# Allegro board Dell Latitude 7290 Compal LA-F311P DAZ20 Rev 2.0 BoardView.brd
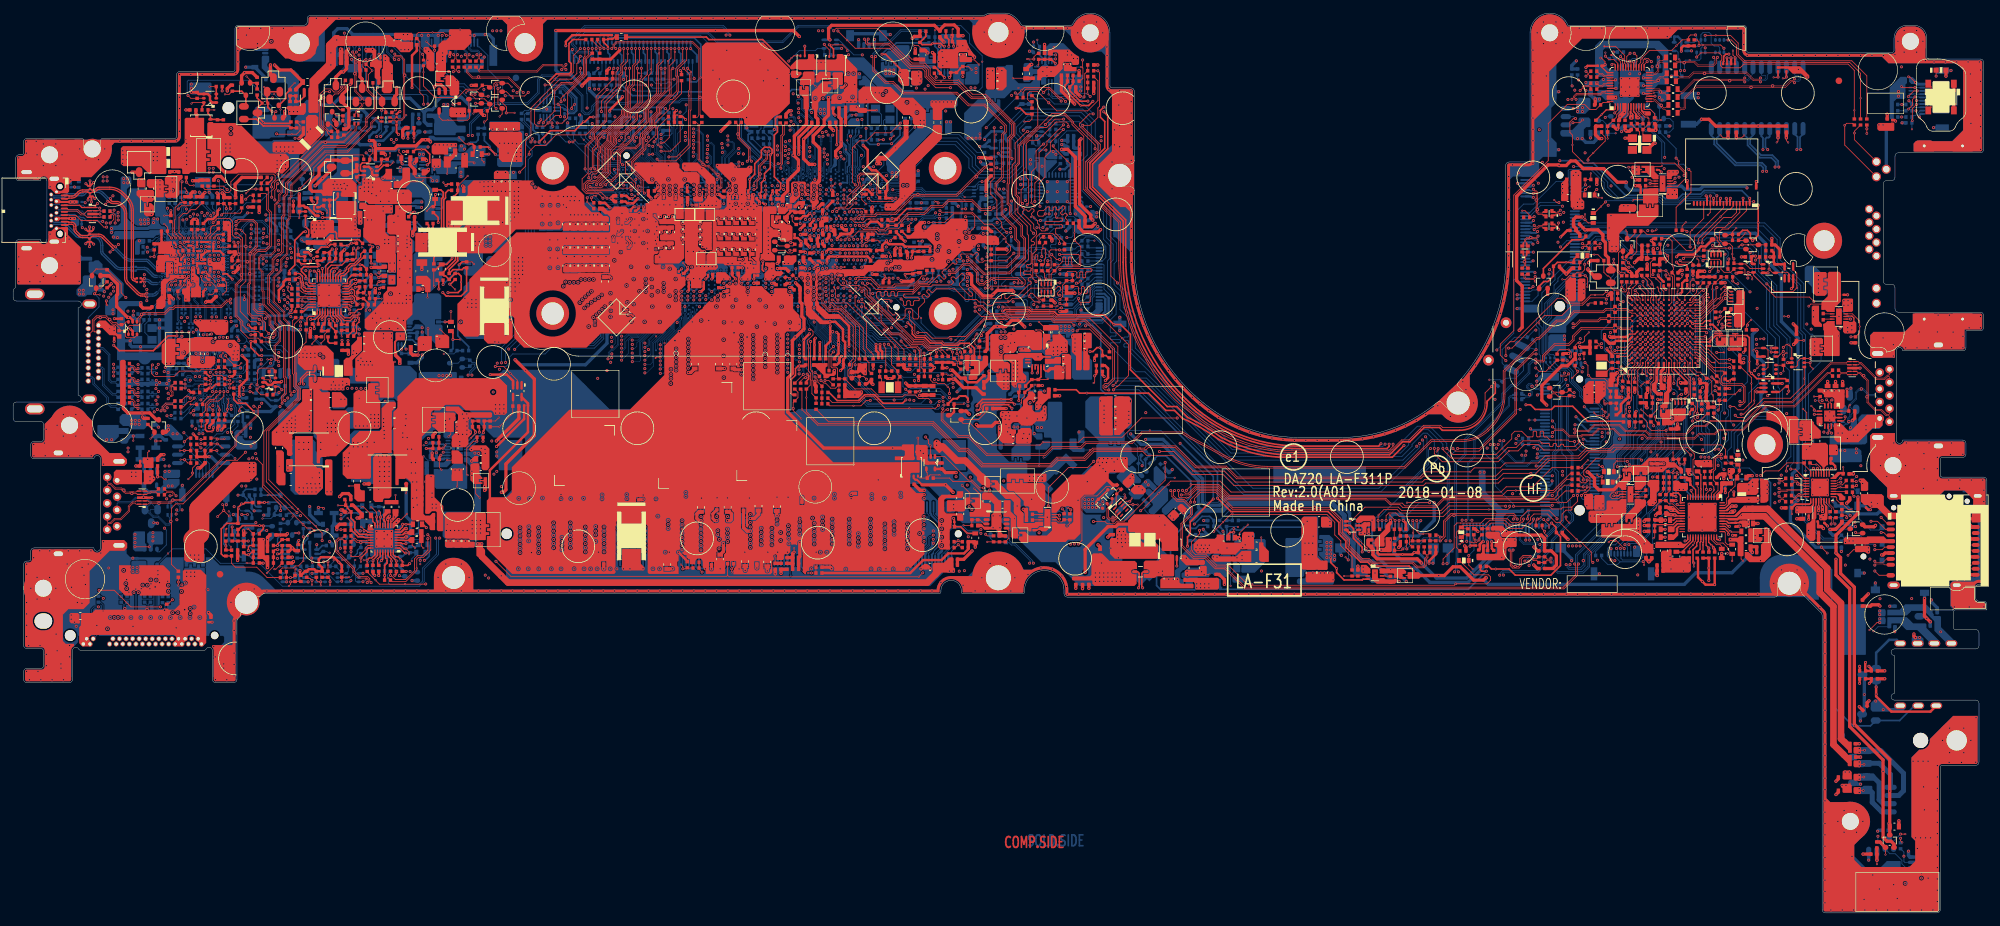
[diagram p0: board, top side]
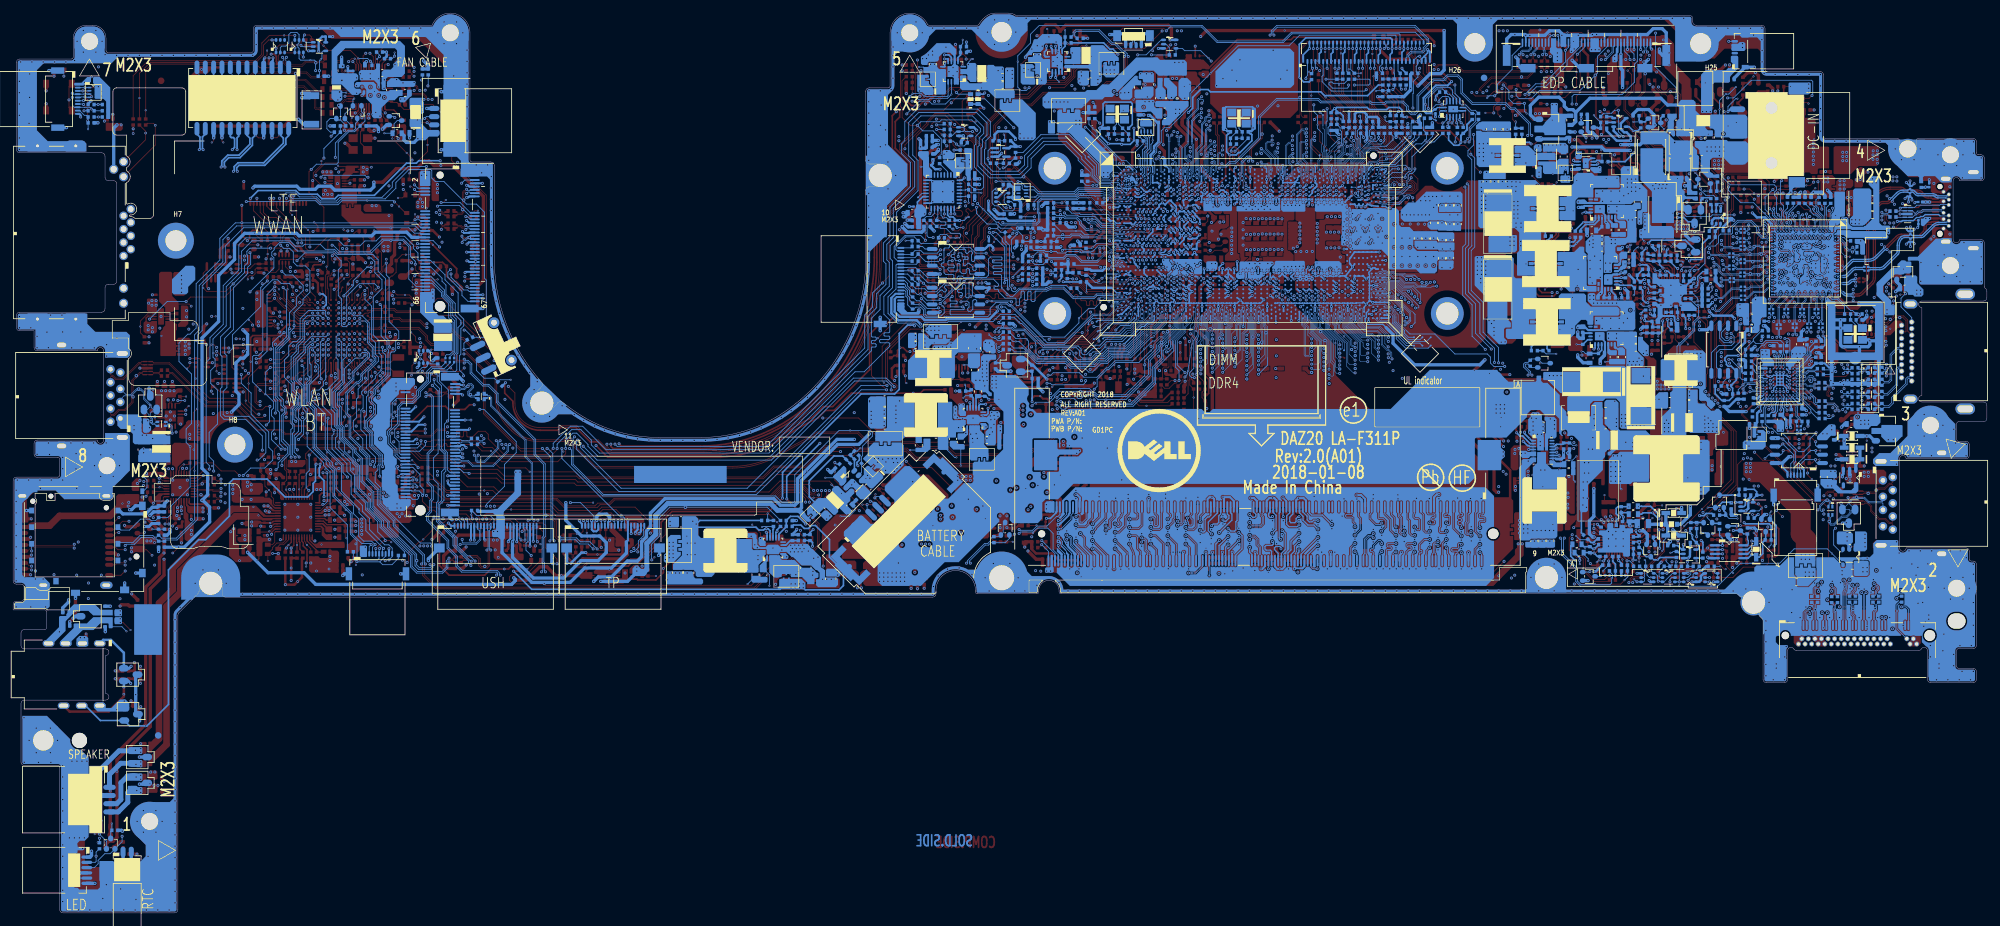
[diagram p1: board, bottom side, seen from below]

Outline 300.7 x 137.2 mm; copper layers: TOP, GND1, IN1, GND2, IN2, IN3, VCC, IN4, GND3, BOTTOM. Coordinates in mm from the lower left corner of the outline.

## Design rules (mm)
net group 20: nets DDR_DRAMRST#_R EMMC_RCOMP
net group AR_DP1_CTRL_CLK: nets AR_DP1_CTRL_CLK AR_DP1_CTRL_DATA
net group CPU_DP1_0: nets CPU_DP1_N0 CPU_DP1_P0
net group CPU_DP1_0_C: nets CPU_DP1_N0_C CPU_DP1_P0_C
net group CPU_DP1_1_C: nets CPU_DP1_N1_C CPU_DP1_P1_C
net group CPU_DP1_2: nets CPU_DP1_N2 CPU_DP1_P2
net group CPU_DP1_2_C: nets CPU_DP1_N2_C CPU_DP1_P2_C
net group CPU_DP1_3: nets CPU_DP1_N3 CPU_DP1_P3
net group CPU_DP1_3_C: nets CPU_DP1_N3_C CPU_DP1_P3_C
net group CPU_DP1_AUX_C: nets CPU_DP1_AUXN_C CPU_DP1_AUXP_C
net group DIFFPAIR2: nets PCIE_PRX_DTX_N1 PCIE_PRX_DTX_P1
net group DIFFPAIR4: nets USB20_N9 USB20_P9
net group DIFFPAIR5: nets USB3_PRX_DTX_N6 USB3_PRX_DTX_P6
net group DIFFPAIR6: nets USB3_PTX_DRX_N6 USB3_PTX_DRX_P6
net group DIFFPAIR7: nets TBTA_USB20_N_R TBTA_USB20_P_R
net group DIFFPAIR8: nets USB20_N9_R USB20_P9_R
net group DIFFPAIR9: nets SW_USB20_N9 SW_USB20_P9
net group DIFFPAIR17: nets N18278920 N18278998
net group DIFFPAIR18: nets USB3_PTX_C_DRX_N6 USB3_PTX_C_DRX_P6
net group HDMI_CTRL_CLK: nets HDMI_CTRL_CLK HDMI_CTRL_DATA
net group INT_SPK_L: nets INT_SPK_L+ INT_SPK_L-
net group INT_SPK_R: nets INT_SPK_R+ INT_SPK_R-
net group INT_SPKR_L: nets INT_SPKR_L+ INT_SPKR_L-
net group INT_SPKR_R: nets INT_SPKR_R+ INT_SPKR_R-
net group ISH_I2C2_SCL: nets ISH_I2C2_SCL ISH_I2C2_SDA
net group LAN_MDI0: nets LAN_MDIN0 LAN_MDIP0
net group LAN_MDI0_L: nets LAN_MDIN0_L LAN_MDIP0_L
net group LAN_MDI1: nets LAN_MDIN1 LAN_MDIP1
net group LAN_MDI1_L: nets LAN_MDIN1_L LAN_MDIP1_L
net group LAN_MDI2: nets LAN_MDIN2 LAN_MDIP2
net group LAN_MDI2_L: nets LAN_MDIN2_L LAN_MDIP2_L
net group LAN_MDI3: nets LAN_MDIN3 LAN_MDIP3
net group LAN_MDI3_L: nets LAN_MDIN3_L LAN_MDIP3_L
net group LPSS_UART2_XD: nets LPSS_UART2_RXD LPSS_UART2_TXD
net group MEM_SMB: nets MEM_SMBCLK MEM_SMBDATA
net group MSCLK: nets MSCLK MSDATA
net group PBAT_CHARGER_SMB: nets PBAT_CHARGER_SMBCLK PBAT_CHARGER_SMBDAT
net group PCIE_PRX_C_DTX_5: nets PCIE_PRX_C_DTX_N5 PCIE_PRX_C_DTX_P5
net group PCIE_PRX_C_DTX_6: nets PCIE_PRX_C_DTX_N6 PCIE_PRX_C_DTX_P6
net group PCIE_PRX_C_DTX_7: nets PCIE_PRX_C_DTX_N7 PCIE_PRX_C_DTX_P7
net group PCIE_PRX_C_DTX_8: nets PCIE_PRX_C_DTX_N8 PCIE_PRX_C_DTX_P8
net group PCIE_PRX_DTX_3: nets PCIE_PRX_DTX_N3 PCIE_PRX_DTX_P3
net group PCIE_PRX_DTX_5: nets PCIE_PRX_DTX_N5 PCIE_PRX_DTX_P5
net group PCIE_PRX_DTX_6: nets PCIE_PRX_DTX_N6 PCIE_PRX_DTX_P6
net group PCIE_PRX_DTX_7: nets PCIE_PRX_DTX_N7 PCIE_PRX_DTX_P7
net group PCIE_PRX_DTX_8: nets PCIE_PRX_DTX_N8 PCIE_PRX_DTX_P8
net group PCIE_PTX_C_DRX_3: nets PCIE_PTX_C_DRX_N3 PCIE_PTX_C_DRX_P3
net group PCIE_PTX_C_DRX_5: nets PCIE_PTX_C_DRX_N5 PCIE_PTX_C_DRX_P5
net group PCIE_PTX_C_DRX_6: nets PCIE_PTX_C_DRX_N6 PCIE_PTX_C_DRX_P6
net group PCIE_PTX_C_DRX_7: nets PCIE_PTX_C_DRX_N7 PCIE_PTX_C_DRX_P7
net group PCIE_PTX_C_DRX_8: nets PCIE_PTX_C_DRX_N8 PCIE_PTX_C_DRX_P8
net group PCIE_PTX_DRX_3: nets PCIE_PTX_DRX_N3 PCIE_PTX_DRX_P3
net group PCIE_PTX_DRX_5: nets PCIE_PTX_DRX_N5 PCIE_PTX_DRX_P5
net group PCIE_PTX_DRX_6: nets PCIE_PTX_DRX_N6 PCIE_PTX_DRX_P6
net group PCIE_PTX_DRX_7: nets PCIE_PTX_DRX_N7 PCIE_PTX_DRX_P7
net group PCIE_PTX_DRX_8: nets PCIE_PTX_DRX_N8 PCIE_PTX_DRX_P8
net group REM_DIODE1: nets REM_DIODE1_N REM_DIODE1_P
net group REM_DIODE2: nets REM_DIODE2_N REM_DIODE2_P
net group REM_DIODE4: nets REM_DIODE4_N REM_DIODE4_P
net group RJ45_MDI0: nets RJ45_MDIN0 RJ45_MDIP0
net group RJ45_MDI1: nets RJ45_MDIN1 RJ45_MDIP1
net group RJ45_MDI2: nets RJ45_MDIN2 RJ45_MDIP2
net group RJ45_MDI3: nets RJ45_MDIN3 RJ45_MDIP3
net group SENSE: nets VCC_GT_SENSE VSS_GT_SENSE
net group SML0_SMB: nets SML0_SMBCLK SML0_SMBDATA
net group SML1_SMB: nets SML1_SMBCLK SML1_SMBDATA
net group TBTA_AUX: nets TBTA_AUXN TBTA_AUXP
net group TBTA_AUX_C: nets TBTA_AUXN_C TBTA_AUXP_C
net group TBTA_LSX_R: nets TBTA_LSRX_R TBTA_LSTX_R
net group TBTA_USB20: nets TBTA_USB20_N TBTA_USB20_P
net group UPD1_SMBD: nets UPD1_SMBCLK_Q UPD1_SMBDAT_Q
net group USB3_PRX_DTX_2: nets USB3_PRX_DTX_N2 USB3_PRX_DTX_P2
net group USB3_PRX_DTX_3: nets USB3_PRX_DTX_N3 USB3_PRX_DTX_P3
net group USB3_PRX_L_DTX_2: nets USB3_PRX_L_DTX_N2 USB3_PRX_L_DTX_P2
net group USB3_PTX_C_DRX_2: nets USB3_PTX_C_DRX_N2 USB3_PTX_C_DRX_P2
net group USB3_PTX_C_DRX_3: nets USB3_PTX_C_DRX_N3 USB3_PTX_C_DRX_P3
net group USB3_PTX_DRX_2: nets USB3_PTX_DRX_N2 USB3_PTX_DRX_P2
net group USB3_PTX_DRX_3: nets USB3_PTX_DRX_N3 USB3_PTX_DRX_P3
net group USB3_PTX_L_DRX_2: nets USB3_PTX_L_DRX_N2 USB3_PTX_L_DRX_P2
net group USB20_1: nets USB20_N1 USB20_P1
net group USB20_2: nets USB20_N2 USB20_P2
net group USB20_2_R: nets USB20_N2_R USB20_P2_R
net group USB20_4: nets USB20_N4 USB20_P4
net group USB20_4_L: nets USB20_N4_L USB20_P4_L
net group USB20_5: nets USB20_N5 USB20_P5
net group USB20_5_R: nets USB20_N5_R USB20_P5_R
net group USB20_7: nets USB20_N7 USB20_P7
net group USB20_7_L: nets USB20_N7_L USB20_P7_L
net group USB20_8: nets USB20_N8 USB20_P8
net group USB20_8_R: nets USB20_N8_R USB20_P8_R
net group USB20_10: nets USB20_N10 USB20_P10
net group VCCSENSE: nets VCCSENSE VSSSENSE
net group VSA_SEN: nets VSA_SEN+ VSA_SEN-
net group VSSIO_SENSE: nets VCCIO_SENSE VSSIO_SENSE
net group 10: nets AUD_HP_NB_SENSE AUD_HP_OUT_L AUD_HP_OUT_L1 AUD_HP_OUT_R AUD_HP_OUT_R1 AUD_SENSE_A
net group 15: nets BC_CLK_ECE1117 CLK_TP_SIO_R CPU_DP2_CTRL_CLK CPU_XDP_TCLK DAT_TP_SIO_I2C_CLK DDR_XDP_WAN_SMBCLK DMIC_CLK0 ESPI_CLK_5105 HDA_BIT_CLK HDA_BIT_CLK_R I2C1_SCK_TP_R JTAG_CLK PCH_JTAG_TCK PCI_CLK_LPC1 SUSCLK SUSCLK_R TBT_I2C_SCL TBT_ROM_CLK WIGIG_32KHZ XCLK_BIASREF XDP_JTAGX
net group AR-90H: nets TBTA_RX1N TBTA_RX1P TBTA_RX2N TBTA_RX2P TBTA_TX1N TBTA_TX1N_C TBTA_TX1P TBTA_TX1P_C TBTA_TX2N TBTA_TX2N_C TBTA_TX2P TBTA_TX2P_C
net group AR-TBT: nets TBTA_BOT_N TBTA_BOT_N_R TBTA_BOT_P TBTA_BOT_P_R TBTA_LSRX TBTA_LSTX TBTA_TOP_N TBTA_TOP_N_R TBTA_TOP_P TBTA_TOP_P_R
net group AR_HDMI: nets AR_DP1_N0 AR_DP1_N1 AR_DP1_N2 AR_DP1_N3 AR_DP1_P0 AR_DP1_P1 AR_DP1_P2 AR_DP1_P3 HDMI_CLKN HDMI_CLKP HDMI_L_CLKN HDMI_L_CLKP HDMI_L_TX_N0 HDMI_L_TX_N1 HDMI_L_TX_N2 HDMI_L_TX_P0 HDMI_L_TX_P1 HDMI_L_TX_P2 HDMI_TX_N0 HDMI_TX_N1 HDMI_TX_N2 HDMI_TX_P0 HDMI_TX_P1 HDMI_TX_P2
net group ASYNC: nets H_CATERR# H_THERMTRIP# H_VCCST_PWRGD_XDP PCH_PLTRST# PCH_PLTRST#_5105 PCH_PLTRST#_AND PCH_PLTRST#_EC PLTRST_LAN# PLTRST_TPM# VCCST_PWRGD XDP_OBS0 XDP_OBS0_R XDP_OBS1 XDP_OBS1_R
net group CL_IAMT: nets PCH_CL_CLK1 PCH_CL_DATA1 PCH_CL_RST1#
net group DDR_XDP_WAN_SMB: nets DDR_XDP_WAN_SMBDAT
net group DDRA_CKE: nets DDR_A_CKE0 DDR_A_CKE1 DDR_A_CKE2 DDR_A_CKE3
net group DDRA_CLK: nets DDR_A_CLK0 DDR_A_CLK1 DDR_A_CLK#0 DDR_A_CLK#1
net group DDRA_CMD: nets DDR_A_ACT# DDR_A_ALERT# DDR_A_BA0 DDR_A_BA1 DDR_A_BG0 DDR_A_BG1 DDR_A_MA0 DDR_A_MA1 DDR_A_MA2 DDR_A_MA3 DDR_A_MA4 DDR_A_MA5 DDR_A_MA6 DDR_A_MA7 DDR_A_MA8 DDR_A_MA9 DDR_A_MA10 DDR_A_MA11 DDR_A_MA12 DDR_A_MA13 DDR_A_MA14 DDR_A_MA15 DDR_A_MA16 DDR_A_PARITY
net group DDRA_CTL: nets DDR_A_CS#0 DDR_A_CS#1 DDR_A_ODT0 DDR_A_ODT1
net group DDRA_D0: nets DDR_A_D0 DDR_A_D1 DDR_A_D2 DDR_A_D3 DDR_A_D4 DDR_A_D5 DDR_A_D6 DDR_A_D7
net group DDRA_D1: nets DDR_A_D8 DDR_A_D9 DDR_A_D10 DDR_A_D11 DDR_A_D12 DDR_A_D13 DDR_A_D14 DDR_A_D15
net group DDRA_D2: nets DDR_A_D16 DDR_A_D17 DDR_A_D18 DDR_A_D19 DDR_A_D20 DDR_A_D21 DDR_A_D22 DDR_A_D23
net group DDRA_D3: nets DDR_A_D24 DDR_A_D25 DDR_A_D26 DDR_A_D27 DDR_A_D28 DDR_A_D29 DDR_A_D30 DDR_A_D31
net group DDRA_D4: nets DDR_A_D32 DDR_A_D33 DDR_A_D34 DDR_A_D35 DDR_A_D36 DDR_A_D37 DDR_A_D38 DDR_A_D39
net group DDRA_D5: nets DDR_A_D40 DDR_A_D41 DDR_A_D42 DDR_A_D43 DDR_A_D44 DDR_A_D45 DDR_A_D46 DDR_A_D47
net group DDRA_D6: nets DDR_A_D48 DDR_A_D49 DDR_A_D50 DDR_A_D51 DDR_A_D52 DDR_A_D53 DDR_A_D54 DDR_A_D55
net group DDRA_D7: nets DDR_A_D56 DDR_A_D57 DDR_A_D58 DDR_A_D59 DDR_A_D60 DDR_A_D61 DDR_A_D62 DDR_A_D63
net group DDRA_DQS: nets DDR_A_DQS0 DDR_A_DQS1 DDR_A_DQS2 DDR_A_DQS3 DDR_A_DQS4 DDR_A_DQS5 DDR_A_DQS6 DDR_A_DQS7 DDR_A_DQS#0 DDR_A_DQS#1 DDR_A_DQS#2 DDR_A_DQS#3 DDR_A_DQS#4 DDR_A_DQS#5 DDR_A_DQS#6 DDR_A_DQS#7
net group DIFF_CLK: nets CLK_ITPXDP_N CLK_ITPXDP_N_R CLK_ITPXDP_P CLK_ITPXDP_P_R CLK_PCIE_N1 CLK_PCIE_N3 CLK_PCIE_N4 CLK_PCIE_N5 CLK_PCIE_P1 CLK_PCIE_P3 CLK_PCIE_P4 CLK_PCIE_P5
net group DMIC: nets DMIC_CLK_CODEC
net group DMIC_CLK: nets DMIC0
net group DP: nets CPU_DP1_AUXN CPU_DP1_AUXP CPU_DP1_N1 CPU_DP1_P1 CPU_DP2_AUXN CPU_DP2_AUXN_C CPU_DP2_AUXP CPU_DP2_AUXP_C CPU_DP2_N0 CPU_DP2_N0_C CPU_DP2_N1 CPU_DP2_N1_C CPU_DP2_N2 CPU_DP2_N2_C CPU_DP2_N3 CPU_DP2_N3_C CPU_DP2_P0 CPU_DP2_P0_C CPU_DP2_P1 CPU_DP2_P1_C CPU_DP2_P2 CPU_DP2_P2_C CPU_DP2_P3 CPU_DP2_P3_C
net group EDP: nets EDP_AUXN EDP_AUXN_C EDP_AUXP EDP_AUXP_C EDP_TXN0 EDP_TXN0_C EDP_TXN1 EDP_TXN1_C EDP_TXP0 EDP_TXP0_C EDP_TXP1 EDP_TXP1_C
net group ESPI: nets ESPI_ALERT# ESPI_CLK ESPI_CS# ESPI_IO0 ESPI_IO0_R ESPI_IO1 ESPI_IO1_R ESPI_IO2 ESPI_IO2_R ESPI_IO3 ESPI_IO3_R ESPI_RESET#
net group HDA_5_15: nets HDA_RST# HDA_RST#_R HDA_SDIN0 HDA_SDIN0_R HDA_SDOUT HDA_SDOUT_R HDA_SYNC HDA_SYNC_R
net group I2C: nets CLK_TP_SIO_I2C_DAT I2C1_SCK_TP I2C1_SDA_TP
net group PCIE: nets CLK_PCIE_N0 CLK_PCIE_P0 PCIE_PRX_C_DTX_N1 PCIE_PRX_C_DTX_N4 PCIE_PRX_C_DTX_P1 PCIE_PRX_C_DTX_P4 PCIE_PRX_DTX_N4 PCIE_PRX_DTX_N9 PCIE_PRX_DTX_N10 PCIE_PRX_DTX_P4 PCIE_PRX_DTX_P9 PCIE_PRX_DTX_P10 PCIE_PTX_C_DRX_N1 PCIE_PTX_C_DRX_N4 PCIE_PTX_C_DRX_N9 PCIE_PTX_C_DRX_N10 PCIE_PTX_C_DRX_P1 PCIE_PTX_C_DRX_P4 PCIE_PTX_C_DRX_P9 PCIE_PTX_C_DRX_P10 PCIE_PTX_DRX_N1 PCIE_PTX_DRX_N4 PCIE_PTX_DRX_N9 PCIE_PTX_DRX_N10 PCIE_PTX_DRX_P1 PCIE_PTX_DRX_P4 PCIE_PTX_DRX_P9 PCIE_PTX_DRX_P10
net group RTC: nets PCH_RTCRST# PCH_RTCX1 PCH_RTCX2 PCH_RTCX2_R SRTCRST#
net group SATA: nets PCIE_PRX_DTX_N11 PCIE_PRX_DTX_N12 PCIE_PRX_DTX_P11 PCIE_PRX_DTX_P12 PCIE_PTX_C_DRX_N11 PCIE_PTX_C_DRX_N12 PCIE_PTX_C_DRX_P11 PCIE_PTX_C_DRX_P12 PCIE_PTX_DRX_N11 PCIE_PTX_DRX_N12 PCIE_PTX_DRX_P11 PCIE_PTX_DRX_P12
net group SD: nets SD/MMCCD# SD/MMCCLK SD/MMCCLK_R SD/MMCCMD SD/MMCDAT2 SD/MMCDAT2_R SD/MMCDAT3 SD/MMCDAT3_R SDWP
net group SD-DIFF: nets SD/MMCDAT0/RCLK+ SD/MMCDAT0/RCLK+_R SD/MMCDAT1/RCLK- SD/MMCDAT1/RCLK-_R SD_UHS2_D0N SD_UHS2_D0P SD_UHS2_D1N SD_UHS2_D1P
net group SMB: nets CPU_DP1_CTRL_CLK CPU_DP1_CTRL_DATA CPU_DP2_CTRL_DATA PBAT_SMBCLK_C PBAT_SMBDAT_C PCH_SMB_ALERT# UPD1_SMBCLK UPD1_SMBDAT UPD2_SMBCLK UPD2_SMBDAT
net group SPI: nets PCH_SPI_CLK PCH_SPI_CLK_0_R PCH_SPI_CLK_1_R PCH_SPI_CLK_2_R PCH_SPI_CLK_R1 PCH_SPI_CS#0 PCH_SPI_CS#0_R1 PCH_SPI_CS#0_R2 PCH_SPI_CS#1 PCH_SPI_CS#1_R1 PCH_SPI_CS#1_R2 PCH_SPI_CS#2 PCH_SPI_CS#2_R PCH_SPI_D0 PCH_SPI_D0_0_R PCH_SPI_D0_1_R PCH_SPI_D0_2_R PCH_SPI_D0_R1 PCH_SPI_D1 PCH_SPI_D1_0_R PCH_SPI_D1_1_R PCH_SPI_D1_2_R PCH_SPI_D1_R1 PCH_SPI_D2 PCH_SPI_D2_0_R PCH_SPI_D2_1_R PCH_SPI_D2_R1 PCH_SPI_D3 PCH_SPI_D3_0_R PCH_SPI_D3_1_R PCH_SPI_D3_R1 PCH_SPI_DO2_XDP PCH_SPI_DO_XDP RESET_OUT#_R
net group SVID: nets H_CPU_SVIDALRT# VIDALERT_N VIDSCLK VIDSOUT
net group TBT_I2C_SCL: nets TBT_I2C_SDA
net group UART: nets ISH_UART0_CTS# ISH_UART0_CTS#_R ISH_UART0_RTS# ISH_UART0_RTS#_R ISH_UART0_RXD ISH_UART0_RXD_R ISH_UART0_TXD ISH_UART0_TXD_R
net group UIM: nets UIM_CLK UIM_DATA UIM_RESET
nets with their own width: min track width 0.203; nets TBTA_CC1 TBTA_CC2
nets with their own width: min track width 0.254; nets +1.0V_APLLEBB +1.0V_PRIM_XDP +1.0V_VCCSTG +1.0V_VCCSTG_R +1.8V_3.3V_ALW_VTR3 +3.3V_1.8V_PGPPA +3.3V_1.8V_PGPPG +3.3V_ALW2 +3.3V_RUN_DIMM1 +3.3V_TBT_FLASH_R +3.3V_VCCHDA +3.3V_VDD_PIC +5V_ALW2 +5V_TBT_VBUS +5V_TBTA_VBUS_D +AC_IN CSI2_COMP OTGEN/CMIN
nets with their own width: min track width 0.305; nets +RREF
nets with their own width: min track width 0.381; nets CFG_RCOMP CPU_POPIRCOMP EDP_COMP EDRAM_OPIO_RCOMP EOPIO_RCOMP HP_OUT_L HP_OUT_R PCH_POPIRCOMP PCIE_RCOMPN PCIE_RCOMPP SD_RCOMP SM_RCOMP0 SM_RCOMP1 SM_RCOMP2
nets with their own width: min track width 0.508; nets +0.6VSP +0.9V_LAN +0.9V_TBT_CIO +0.9V_TBT_DP +0.9V_TBT_LVR_OUT +0.9V_TBT_PCIE +0.9V_TBT_SVR +0.9V_TBT_USB +1.0V_AMPHYPLL +1.0V_APLL +1.0V_CLK1 +1.0V_CLK2 +1.0V_CLK3 +1.0V_CLK4 +1.0V_CLK5 +1.0V_CLK6 +1.0V_DTS +1.0V_MPHYAON +1.0V_PRIM_CORE +1.0V_PRIM_COREP +1.0V_VCCST +1.0V_VCCST_C +1.0V_VCCSTG_C +1.0VO_DSW +1.2V_DDRP +1.2V_LDO +1.2V_MEM +1.2V_MEM_CPUCLK +1.8V_PGPPF +1.8V_PRIM +1.8V_RUN +1.8V_RUN_AUDIO +1.8V_RUN_UZ8 +1.8VALWP +1VALWP +1VALWP_B+ +1VS_VCCIOP +2.5V_MEM +2.5V_VIN +3.3V_1.8V_ESPI +3.3V_ALW +3.3V_ALW_DSW +3.3V_ALW_PCH +3.3V_ALW_PCH_UZ3 +3.3V_ALW_UE1 +3.3V_ALWP +3.3V_EC_PLL +3.3V_LAN_OUT +3.3V_LAN_UZ2 +3.3V_PDA_VOUT +3.3V_PGPPB +3.3V_PGPPC +3.3V_PGPPD +3.3V_PGPPE +3.3V_RTC_LDO +3.3V_RUN +3.3V_RUN_AUDIO +3.3V_RUN_AUDIO_DVDD +3.3V_RUN_AUDIO_IO +3.3V_RUN_AUDIO_UZ5 +3.3V_RUN_UZ3 +3.3V_SPI +3.3V_TBT_LC +3.3V_TBT_SX +3.3V_TBTA_FLASH +3.3V_TP +3.3V_TSP +3.3V_VDD_DCIN +5V_ALW +5V_ALW_PDA +5V_ALWP +5V_PD_VDD +5V_RUN +5V_RUN_AUDIO_UZ5 +BL_PWR_SRC +CHARGER_SRC +COINCELL +DC_IN +DC_IN_SS +DCIN_JACK +DCPRTC +DDR_VREF_A_CA +DDR_VREF_A_DQ +DDR_VREF_CA +EC_DEBUG_VCC +EDP_VDD +GND_CHASSIS +LCDVDD +PBATT +PECI_VREF +PWR_SRC +PWR_SRC_AC +PWR_SRC_R +REGCTL_PNP10 +RSVD_VCC3P3_1 +RTC_CELL +RTC_CELL_VBAT +SDC_IN +SDREG2 +SIM_PWR +TBT_SVR_IND +TBTA_LDO_BMC +TBTA_VBUS_1 +UZ12_TPM +VBUS_DC_SS +VCC1V8A_TBTA_LDO +VCC1V8D_TBTA_LDO +VCC3V3_ANA_PCIE +VCC3V3_ANA_USB2 +VCC_1P8 +VCC_CORE +VCC_CORE_G0 +VCC_CORE_G1 +VCC_GT +VCC_SA +VCC_SFR_OC +VCHGR +VDDA_AVDD1 +VR_CAP +VSS_PLL +Z4012 CPU_B+ GND GNDA Z2805 Z2806 Z2807 Z2808
nets with their own width: min track width 0.762; nets +1.0V_SRAM
nets with their own width: min track width 1.016; nets +0.6V_DDR_VTT +1.8V_RUN_CARD +3.3V_CAM +3.3V_MMI_IN +3.3V_RUN_CARD +VHDMI_VCC RING2 RING2_R SLEEVE SLEEVE_R
nets with their own width: min track width 1.524; nets +3.3V_LAN +3.3V_TBT +3.3V_TBT_S0 +5V_RUN_PVDD_L
nets with their own width: min track width 2.032; nets +1.0V_MPHYGT +3.3V_WLAN +3.3V_WLAN_UZ2 +3.3V_WWAN +5V_RUN_AUDIO +5V_RUN_UZ4 +5V_USB_CHG_PWR +USB_EX2_PWR
nets with their own width: min track width 2.54; nets +3.3V_WWAN_UZ4
nets with their own width: min track width 3.048; nets +1.0VS_VCCIO +3.3V_HDD_M2
nets with their own width: min track width 4.064; nets +1.0V_PRIM
nets with their own width: min track width 5.08; nets +TBTA_VBUS

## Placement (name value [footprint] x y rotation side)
CA1  680P_0402_50V7K  [C_0402]  286.7 43.62 90 bottom
CA2  330P_0402_50V8J  [C_0402]  283.09 35.7 0 top
CA3  330P_0402_50V8J  [C_0402]  283.09 36.9 0 top
CA4  680P_0402_50V7K  [C_0402]  286.7 45.85 90 bottom
CA5  100P_0402_50V8J  [C_0402]  53.76 129.41 0 top
CA6  100P_0402_50V8J  [C_0402]  53.76 128.53 180 top
CA7  0.1U_0201_10V6K  [C_0201]  55.97 130.31 270 top
CA8  0.1U_0201_10V6K  [C_0201]  252.44 55.8 270 top
CA9  10U_0603_10V6M  [C_0603]  251.48 55.95 270 top
CA10  0.1U_0201_10V6K  [C_0201]  260.27 64.72 0 top
CA12  680P_0402_50V7K  [C_0402]  291.16 43.76 0 bottom
CA13  680P_0402_50V7K  [C_0402]  293.14 45.78 270 bottom
CA19  1000P_0402_50V7K  [C_0402]  278.99 20.71 180 top
CA22  1000P_0402_50V7K  [C_0402]  279.79 23.76 0 top
CA23  1000P_0402_50V7K  [C_0402]  279.73 25.79 0 top
CA24  1000P_0402_50V7K  [C_0402]  278.99 18.68 180 top
CA25  10U_0603_10V6M  [C_0603]  252.44 59.89 180 top
CA27  0.1U_0402_25V6  [C_0402]  251.8 63.78 270 top
CA28  0.1U_0402_25V6  [C_0402]  250.91 63.78 270 top
CA29  1U_0603_10V6K  [C_0603]  261.9 54.75 90 top
CA31  1U_0603_10V6K  [C_0603]  262.66 66.37 0 top
CA33  10P_0402_50V8J  [C_0402]  257.71 67.31 90 top
CA35  2.2U_0402_6.3V6M  [C_0402]  255.36 55.01 270 top
CA41  0.1U_0402_25V6  [C_0402]  252.69 63.78 270 top
CA43  10U_0603_10V6M  [C_0603]  252.41 57.29 180 top
CA44  10U_0603_10V6M  [C_0603]  252.41 58.49 180 top
CA45  0.1U_0201_10V6K  [C_0201]  262.41 59.49 270 top
CA46  10U_0603_10V6M  [C_0603]  263.68 59.38 0 top
CA47  0.1U_0201_10V6K  [C_0201]  262.15 63.09 90 top
CA48  10U_0603_10V6M  [C_0603]  265.14 63 0 top
CA49  1U_0603_10V6K  [C_0603]  260.31 55.51 270 top
CA51  10U_0603_10V6M  [C_0603]  253.39 55.07 270 top
CA52  10U_0603_10V6M  [C_0603]  263.29 58.18 0 top
CA53  10U_0603_10V6M  [C_0603]  256.63 67.32 90 top
CA54  82P_0402_50V8J  [C_0402]  258.6 67.31 90 top
CA55  0.1U_0201_10V6K  [C_0201]  255.52 65.29 180 top
CA56  10U_0603_10V6M  [C_0603]  255.23 66.11 90 top
CA57  0.1U_0201_10V6K  [C_0201]  262.47 57 90 top
CA58  10U_0603_10V6M  [C_0603]  263.29 56.97 0 top
CA59  10U_0603_10V6M  [C_0603]  265.14 64.21 0 top
CA60  0.1U_0201_10V6K  [C_0201]  265.73 66.05 0 top
CA61  10U_0603_10V6M  [C_0603]  260.63 65.48 90 top
CA62  100P_0402_50V8J  [C_0402]  251.43 64.68 180 top
CA63  12P_0402_50V8J  [C_0402]  265.63 65.29 0 top
CA64  68P_0402_50V8J  [C_0402]  249.64 55.08 270 top
CA65  12P_0402_50V8J  [C_0402]  265.63 55.83 0 top
CA66  68P_0402_50V8J  [C_0402]  265.63 54.94 0 top
CA67  12P_0402_50V8J  [C_0402]  249.58 67.56 90 top
CA68  68P_0402_50V8J  [C_0402]  250.47 67.56 90 top
CA69  33P_0402_50V8J  [C_0402]  263.26 54.68 0 top
CA72  100P_0402_50V8J  [C_0402]  252.3 64.68 0 top
CA78  100P_0402_50V8J  [C_0402]  248.77 55.1 270 top
CC7  33P_0402_50V8J  [C_0402]  156.99 103.09 0 top
CC8  33P_0402_50V8J  [C_0402]  158.14 92.52 90 top
CC9  0.1U_0201_10V6K  [C_0201]  152.04 101.83 90 bottom
CC10  0.1U_0201_10V6K  [C_0201]  151.98 95.35 90 bottom
CC21  12P_0402_50V8J  [C_0402]  114.31 119.1 0 bottom
CC22  12P_0402_50V8J  [C_0402]  113.45 119.1 180 bottom
CC23  15P_0402_50V8J  [C_0402]  135.1 81.74 180 top
CC24  1U_0402_6.3V6K  [C_0402]  129.82 84.48 270 top
CC25  1U_0402_6.3V6K  [C_0402]  128.9 81.8 90 top
CC26  12P_0402_50V8J  [C_0402]  132.03 81.74 0 top
CC27  47P_0402_50V8J  [C_0402]  119.09 78.08 90 top
CC28  0.1U_0201_10V6K  [C_0201]  90.64 133.26 90 top
CC29  0.1U_0201_10V6K  [C_0201]  91.21 133.26 90 top
CC30  0.1U_0201_10V6K  [C_0201]  84.01 122.51 270 bottom
CC32  0.1U_0402_25V6  [C_0402]  89.37 131.09 270 top
CC33  0.1U_0402_25V6  [C_0402]  89.38 128.03 180 bottom
CC176  10U_0402_6.3V6M  [C_0402]  117.63 94.87 90 top
CC177  10U_0402_6.3V6M  [C_0402]  116.23 94.87 90 top
CC178  10U_0402_6.3V6M  [C_0402]  109.79 94.88 180 top
CC179  10U_0402_6.3V6M  [C_0402]  113.5 95.12 90 top
CC195  1U_0402_6.3V6K  [C_0402]  122.59 120.53 180 top
CC199  1U_0402_6.3V6K  [C_0402]  116.35 108.86 180 top
CC202  22U_0402_6.3V6M  [C_0402]  119.15 107.72 270 top
CC203  1U_0402_6.3V6K  [C_0402]  123.34 108.1 270 top
CC204  1U_0402_6.3V6K  [C_0402]  132.54 96.09 0 top
CC205  1U_0402_6.3V6K  [C_0402]  121.36 100.62 270 top
CC206  1U_0402_6.3V6K  [C_0402]  120.74 102.56 90 top
CC207  1U_0402_6.3V6K  [C_0402]  123.59 101.68 180 top
CC208  1U_0402_6.3V6K  [C_0402]  123.39 103.4 0 top
CC209  1U_0402_6.3V6K  [C_0402]  121.61 102.57 0 top
CC210  47U_0805_6.3V6M  [C_0805]  140.71 119.56 0 bottom
CC211  1U_0402_6.3V6K  [C_0402]  123.18 104.84 180 top
CC212  1U_0402_6.3V6K  [C_0402]  132.42 101.05 270 top
CC213  1U_0402_6.3V6K  [C_0402]  120.04 97.43 90 top
CC214  0.1U_0201_10V6K  [C_0201]  131.81 84.59 0 top
CC215  1U_0402_6.3V6K  [C_0402]  149.05 103 90 top
CC216  1U_0402_6.3V6K  [C_0402]  126.21 120.53 180 bottom
CC217  1U_0402_6.3V6K  [C_0402]  119.96 100.83 90 top
CC218  1U_0402_6.3V6K  [C_0402]  121.43 104.87 180 top
CC219  47U_0805_6.3V6M  [C_0805]  127.79 125.5 90 bottom
CC220  47U_0805_6.3V6M  [C_0805]  124.18 125.07 270 bottom
CC221  47U_0805_6.3V6M  [C_0805]  125.89 125.07 270 bottom
CC222  1U_0402_6.3V6K  [C_0402]  126.95 104.15 0 top
CC223  0.1U_0201_10V6K  [C_0201]  126.76 97.22 180 top
CC224  1U_0402_6.3V6K  [C_0402]  131.6 98.26 270 top
CC225  47U_0805_6.3V6M  [C_0805]  126.12 121.93 180 bottom
CC226  47U_0805_6.3V6M  [C_0805]  122.4 125.03 270 bottom
CC250  1U_0402_6.3V6K  [C_0402]  107.49 97.34 180 top
CC251  1U_0402_6.3V6K  [C_0402]  107.52 96.25 270 top
CC252  1U_0402_6.3V6K  [C_0402]  115.72 98.88 90 top
CC253  1U_0402_6.3V6K  [C_0402]  114.83 98.88 90 top
CC264  1U_0402_6.3V6K  [C_0402]  124.86 108.52 90 top
CC265  1U_0402_6.3V6K  [C_0402]  124.2 99.92 180 top
CC266  0.01UF_0402_25V7K  [C_0402]  125.8 79.64 0 top
CC269  0.1U_0402_25V6  [C_0402]  91.35 128.09 180 top
CC270  0.1U_0201_10V6K  [C_0201]  126.49 84.34 180 top
CC279  22U_0603_6.3V6M  [C_0603]  138.89 80.36 270 top
CC280  22U_0603_6.3V6M  [C_0603]  140.09 80.36 270 top
CC281  0.1U_0201_10V6K  [C_0201]  129.6 127.39 180 bottom
CC288  1U_0402_6.3V6K  [C_0402]  119.89 95.01 180 top
CC294  22U_0603_6.3V6M  [C_0603]  103.85 84.4 270 top
CC295  22U_0603_6.3V6M  [C_0603]  107.53 84.4 270 top
CC296  22U_0603_6.3V6M  [C_0603]  109.73 84.4 270 top
CC297  10U_0402_6.3V6M  [C_0402]  109.52 98.4 0 top
CC300  100P_0402_50V8J  [C_0402]  85.37 118.87 90 bottom
CC301  100P_0402_50V8J  [C_0402]  90 119.78 270 bottom
CC302  0.1U_0402_25V6  [C_0402]  147.98 115.09 270 bottom
CC303  0.1U_0402_25V6  [C_0402]  99.91 120.23 270 bottom
CC304  0.1U_0402_25V6  [C_0402]  99.02 120.23 270 bottom
CC305  0.1U_0402_25V6  [C_0402]  97.18 119.76 90 bottom
CC306  0.1U_0402_25V6  [C_0402]  88.23 131.09 270 top
CC307  0.1U_0402_25V6  [C_0402]  92.09 128.03 0 bottom
CC308  0.1U_0402_25V6  [C_0402]  99.83 121.42 0 top
CC310  0.1U_0402_25V6  [C_0402]  89.11 119.78 270 bottom
CC312  0.1U_0402_25V6  [C_0402]  95.41 119.77 180 bottom
CC313  0.1U_0201_10V6K  [C_0201]  122.59 98.82 90 top
CC314  0.1U_0201_10V6K  [C_0201]  124.52 104.72 180 top
CC316  33P_0402_50V8J  [C_0402]  149.84 89.86 180 bottom
CC318  33P_0402_50V8J  [C_0402]  141.69 102.39 270 bottom
CC319  33P_0402_50V8J  [C_0402]  141.2 105.23 180 bottom
CC320  33P_0402_50V8J  [C_0402]  133.26 104.79 180 top
CC321  33P_0402_50V8J  [C_0402]  95.41 118.88 180 bottom
CC322  2.2P_0402_50V8C  [C_0402]  136.96 71.09 0 top
CC323  2.2P_0402_50V8C  [C_0402]  125.17 103.45 0 top
CC324  2.2P_0402_50V8C  [C_0402]  137.06 97.43 270 top
CC325  2.2P_0402_50V8C  [C_0402]  127.74 122.82 180 top
CC326  1U_0402_6.3V6K  [C_0402]  137.01 100.85 180 top
CC331  2.2P_0402_50V8C  [C_0402]  122.32 78.54 90 top
CC332  2.2P_0402_50V8C  [C_0402]  120.85 79.88 90 top
CC333  2.2P_0402_50V8C  [C_0402]  123.23 80.31 180 top
CC334  12P_0402_50V8J  [C_0402]  132.92 119.64 0 bottom
CC335  12P_0402_50V8J  [C_0402]  131.67 119.64 180 bottom
CC340  0.1U_0402_25V6K  [C_0402]  145.45 81.48 180 bottom
CC341  22U_0603_6.3V6M  [C_0603]  120.2 108.24 270 top
CD1  10U_0603_10V6M  [C_0603]  108.86 62.56 270 top
CD2  10U_0603_10V6M  [C_0603]  104.8 62.56 270 top
CD3  10U_0603_10V6M  [C_0603]  111.53 54.3 270 top
CD4  10U_0603_10V6M  [C_0603]  114.9 54.24 270 top
CD5  10U_0603_10V6M  [C_0603]  116.36 62.69 270 top
CD6  10U_0603_10V6M  [C_0603]  107.72 53.22 90 top
CD7  10U_0603_10V6M  [C_0603]  99.66 53.86 270 top
CD8  10U_0603_10V6M  [C_0603]  113.56 62.75 270 top
CD9  1U_0402_6.3V6K  [C_0402]  89.98 54.13 270 top
CD10  1U_0402_6.3V6K  [C_0402]  113.31 54.13 270 top
CD11  1U_0402_6.3V6K  [C_0402]  111.28 62.32 270 top
CD12  1U_0402_6.3V6K  [C_0402]  105.48 53.1 0 top
CD13  1U_0402_6.3V6K  [C_0402]  95.34 63.9 270 top
CD14  1U_0402_6.3V6K  [C_0402]  107.21 62.38 270 top
CD15  1U_0402_6.3V6K  [C_0402]  128.29 63.05 90 top
CD16  1U_0402_6.3V6K  [C_0402]  119.26 62.62 0 top
CD17  330U_D3_2.5VY_R6M  [C_D3]  94.19 60.68 270 top
CD18  1U_0402_6.3V6K  [C_0402]  142.64 61.49 270 top
CD19  1U_0402_6.3V6K  [C_0402]  142.64 62.61 90 top
CD20  10U_0603_10V6M  [C_0603]  144.3 62.56 90 top
CD21  10U_0603_10V6M  [C_0603]  144.3 61.54 270 top
CD22  10U_0603_10V6M  [C_0603]  140.42 52.78 180 top
CD23  1U_0402_6.3V6K  [C_0402]  142.95 53.92 0 top
CD24  1U_0402_6.3V6K  [C_0402]  142.95 53.03 0 top
CD25  0.1U_0402_10V6K  [C_0402]  118.76 53.29 0 top
CD26  2.2U_0402_6.3V6M  [C_0402]  118.76 54.18 0 top
CD27  2.2U_0402_6.3V6M  [C_0402]  143.42 58.88 180 top
CD28  0.1U_0201_10V6K  [C_0201]  143.38 59.64 180 top
CD29  0.1U_0402_25V6  [C_0402]  102.7 52.63 90 top
CD31  0.022U_0402_16V7K  [C_0402]  116.99 52.39 90 top
CD32  0.1U_0201_10V6K  [C_0201]  78.44 77.37 180 top
CE3  2200P_0402_50V7K  [C_0402]  256.11 80.78 0 top
CE4  2200P_0402_50V7K  [C_0402]  257.02 79.51 0 top
CE8  .047U_0402_16V7K  [C_0402]  259.28 96.09 0 top
CE10  1U_0402_6.3V6K  [C_0402]  243.36 79.55 90 top
CE11  0.1U_0201_10V6K  [C_0201]  244.47 81.29 180 top
CE12  2.2U_0402_6.3V6M  [C_0402]  244.24 76.86 270 top
CE13  0.1U_0201_10V6K  [C_0201]  258.53 90.3 270 top
CE14  1U_0402_6.3V6K  [C_0402]  243.86 87.78 270 top
CE15  0.1U_0201_10V6K  [C_0201]  252.22 81.16 180 top
CE16  10U_0603_6.3V6M  [C_0603]  253.58 75.26 270 top
CE17  22U_0603_6.3V6M  [C_0603]  250.02 80.21 0 top
CE18  0.1U_0201_10V6K  [C_0201]  250.43 81.16 0 top
CE19  0.1U_0201_10V6K  [C_0201]  251.46 95.65 90 top
CE20  0.1U_0201_10V6K  [C_0201]  251.65 78.24 180 top
CE21  0.1U_0201_10V6K  [C_0201]  258.53 87.04 270 top
CE22  0.1U_0201_10V6K  [C_0201]  263.9 86.62 270 top
CE23  0.1U_0201_10V6K  [C_0201]  244.6 87.81 270 top
CE24  2200P_0402_50V7K  [C_0402]  244.05 89.62 270 top
CE25  0.1U_0201_10V6K  [C_0201]  255.04 96.44 270 top
CE26  2200P_0402_50V7K  [C_0402]  243.1 91.08 270 top
CE27  2200P_0402_50V7K  [C_0402]  244.05 92.48 270 top
CE28  10P_0402_50V8J  [C_0402]  243.61 83.02 270 top
CE29  10P_0402_50V8J  [C_0402]  243.61 83.95 90 top
CE30  1U_0402_6.3V6K  [C_0402]  249.07 100.9 180 top
CE31  1U_0402_6.3V6K  [C_0402]  254.86 80.8 270 top
CE32  10U_0603_6.3V6M  [C_0603]  238.91 118.95 0 bottom
CE35  100P_0402_50V8J  [C_0402]  119.08 101.05 90 top
CE36  0.1U_0402_25V6  [C_0402]  267.03 101.86 0 top
CE37  100P_0402_50V8J  [C_0402]  237.13 79.78 270 top
CE38  0.1U_0402_25V6  [C_0402]  244.45 93.61 180 top
CE39  100P_0402_50V8J  [C_0402]  69.57 83.36 90 bottom
CE40  4700P_0402_25V7K  [C_0402]  252.73 97.61 0 top
CE46  100P_0402_50V8J  [C_0402]  151.28 56.45 90 bottom
CE47  4700P_0402_25V7K  [C_0402]  255.93 98.77 270 top
CE52  0.1U_0402_25V6K  [C_0402]  264.83 100.02 180 top
CE53  0.1U_0402_25V6K  [C_0402]  268.24 100.02 0 top
CE54  10P_0402_50V8J  [C_0402]  249.01 80.92 270 top
CE57  33P_0402_50V8J  [C_0402]  247.1 74.86 90 top
CE59  12P_0402_50V8J  [C_0402]  252.5 74.7 270 top
CE60  68P_0402_50V8J  [C_0402]  263.05 85.96 270 top
CE61  68P_0402_50V8J  [C_0402]  271.69 87.3 90 top
CE62  4700P_0402_25V7K  [C_0402]  249.72 78.62 180 top
CE63  1U_0402_6.3V6K  [C_0402]  238.11 104.07 180 top
CE64  0.1U_0402_25V6  [C_0402]  238.66 98.31 180 top
CE65  22P_0402_50V8J  [C_0402]  234.68 98.6 0 top
CE66  0.1U_0402_25V6  [C_0402]  259.1 76.21 90 top
CI1  100U_1206_6.3V6M  [C_1206]  19.58 57.11 0 bottom
CI3  0.1U_0201_10V6K  [C_0201]  19.48 65.54 0 top
CI4  0.1U_0402_25V6  [C_0402]  22.13 64.65 0 top
CI5  0.1U_0402_25V6  [C_0402]  22.13 63.76 0 top
CI6  10U_0603_10V6M  [C_0603]  19.77 51.87 0 bottom
CI7  0.1U_0201_10V6K  [C_0201]  18.88 53.5 90 bottom
CI13  0.1U_0402_25V6  [C_0402]  278.1 82.75 180 top
CI14  100U_1206_6.3V6M  [C_1206]  280.76 71.96 270 bottom
CI16  0.1U_0402_25V6  [C_0402]  278.1 81.86 180 top
CI17  0.1U_0201_10V6K  [C_0201]  281.32 75.18 180 bottom
CI19  0.1U_0201_10V6K  [C_0201]  278.81 78.75 0 top
CI29  0.1U_0402_25V6  [C_0402]  229.89 98.32 270 top
CI30  0.1U_0402_25V6  [C_0402]  230.78 98.32 270 top
CI31  10U_0402_6.3V6M  [C_0402]  278.73 79.5 90 top
CI32  150U_B2_6.3VM_R35M  [C_B2]  278.09 72.12 90 bottom
CI33  47U_0603_6.3V6M  [C_0603]  277.65 78.94 90 top
CI34  47U_0603_6.3V6M  [C_0603]  276.44 78.94 90 top
CI43  12P_0402_50V8J  [C_0402]  281.42 73.51 180 bottom
CI44  68P_0402_50V8J  [C_0402]  281.42 74.39 180 bottom
CI45  12P_0402_50V8J  [C_0402]  19.32 66.3 0 top
CI46  68P_0402_50V8J  [C_0402]  19.32 67.19 0 top
CL1  0.1U_0402_25V6  [C_0402]  240.36 128.34 0 top
CL2  0.1U_0402_25V6  [C_0402]  240.36 127.46 0 top
CL3  0.1U_0201_10V6K  [C_0201]  249.71 127.8 90 bottom
CL4  10U_0603_10V6M  [C_0603]  250.66 127.71 90 bottom
CL5  0.1U_0402_25V6  [C_0402]  240.36 126.5 0 top
CL6  0.1U_0402_25V6  [C_0402]  240.36 125.61 0 top
CL7  0.1U_0201_10V6K  [C_0201]  244.56 120.76 270 top
CL8  0.1U_0201_10V6K  [C_0201]  248.88 127.8 90 bottom
CL9  0.1U_0201_10V6K  [C_0201]  247.84 125.23 180 bottom
CL10  0.1U_0201_10V6K  [C_0201]  242 129.17 180 top
CL11  0.1U_0201_10V6K  [C_0201]  244.4 126.5 0 bottom
CL12  22U_0603_6.3V6M  [C_0603]  243.74 128.09 0 bottom
CL13  27P_0402_50V8J  [C_0402]  247.43 119.45 180 top
CL14  27P_0402_50V8J  [C_0402]  248.3 119.45 0 top
CL15  0.1U_0201_10V6K  [C_0201]  253.11 133.61 180 bottom
CL16  0.1U_0201_10V6K  [C_0201]  261.11 129.44 180 top
CL17  0.1U_0201_10V6K  [C_0201]  262.32 129.44 180 top
CL18  470P_0402_50V7K  [C_0402]  285.52 120.14 90 top
CL19  0.1U_0201_10V6K  [C_0201]  286.28 120.31 90 top
CL20  0.1U_0201_10V6K  [C_0201]  268.88 128.31 90 top
CL21  0.1U_0201_10V6K  [C_0201]  270.15 128.31 90 top
CL22  10P_1808_3KV8J  [C_1808]  255.23 124.61 270 bottom
CL28  22U_0805_6.3V6M  [C_0805]  243.04 124.64 90 bottom
CL29  12P_0402_50V8J  [C_0402]  247.1 129.18 270 bottom
CL30  82P_0402_50V8J  [C_0402]  246.91 126.43 90 bottom
CLIP1  -  [CLIP_14P0X2P6]  199.05 66.85 180 bottom
CLIP2  -  [CLIP_7P7X4P2]  280.15 43.2 270 bottom
CMOS1  SHORT PADS~D  [SHORTPADS-NPM]  127.79 82.01 90 top
CN60  68P_0402_50V8J  [C_0402]  29.22 45.1 0 top
CN61  0.1U_0201_10V6K  [C_0201]  29.2 44.33 0 top
CN62  0.1U_0201_10V6K  [C_0201]  10.54 44.33 180 top
CN63  22U_0603_6.3V6M  [C_0603]  10.95 45.29 180 top
CN64  22U_0603_6.3V6M  [C_0603]  28.28 50.43 0 bottom
CN65  0.22U_0402_10V6K  [C_0402]  26.68 47.35 90 bottom
CN66  0.22U_0402_10V6K  [C_0402]  25.8 47.35 90 bottom
CN67  0.22U_0402_10V6K  [C_0402]  23.65 47.31 90 bottom
CN68  0.22U_0402_10V6K  [C_0402]  22.76 47.31 90 bottom
CN69  0.22U_0402_10V6K  [C_0402]  20.92 47.38 90 bottom
CN70  0.22U_0402_10V6K  [C_0402]  20.03 47.38 90 bottom
CN71  0.22U_0402_10V6K  [C_0402]  17.36 47.38 90 bottom
CN72  0.22U_0402_10V6K  [C_0402]  16.47 47.38 90 bottom
CR1  4.7U_0402_6.3V6M  [C_0402]  276.05 69.29 0 top
CR2  0.1U_0201_10V6K  [C_0201]  276.31 68.54 0 top
CR3  0.1U_0201_10V6K  [C_0201]  274.33 59.68 0 top
CR4  10U_0402_6.3V6M  [C_0402]  274.14 57.08 0 top
CR5  4.7U_0603_6.3V6K  [C_0603]  272.57 61.49 270 top
CR6  0.1U_0201_10V6K  [C_0201]  273.56 61.16 270 top
CR7  0.1U_0201_10V6K  [C_0201]  275.92 60.04 270 top
CR11  0.1U_0402_25V6  [C_0402]  270.05 66.25 0 top
CR12  0.1U_0402_25V6  [C_0402]  270.05 65.29 0 top
CR13  0.1U_0402_25V6  [C_0402]  270.03 63.64 0 top
CR14  0.1U_0402_25V6  [C_0402]  270.04 62.7 0 top
CR15  1U_0402_6.3V6K  [C_0402]  278.79 66.94 0 top
CR17  0.1U_0201_10V6K  [C_0201]  282.09 55.79 90 top
CR18  4.7U_0603_6.3V6K  [C_0603]  281.14 55.38 90 top
CR19  0.1U_0201_10V6K  [C_0201]  282.29 61.8 90 top
CR20  4.7U_0603_6.3V6K  [C_0603]  282.01 64.69 270 top
CR21  5P_0402_50V8C  [C_0402]  278.62 60.63 270 top
CR22  1U_0402_6.3V6K  [C_0402]  278.89 63.26 0 top
CR25  12P_0402_50V8J  [C_0402]  274.14 58 0 top
CR26  82P_0402_50V8J  [C_0402]  274.14 58.91 0 top
CR27  12P_0402_50V8J  [C_0402]  276.05 70.19 0 top
CR28  82P_0402_50V8J  [C_0402]  276.05 71.11 0 top
CT1  0.1U_0201_10V6K  [C_0201]  38.96 80.45 0 bottom
CT2  0.22U_0201_6.3V6K  [C_0201]  32.56 91.46 90 bottom
CT3  0.22U_0201_6.3V6K  [C_0201]  33.13 91.46 90 bottom
CT4  0.22U_0201_6.3V6K  [C_0201]  30.85 91.46 90 bottom
CT5  0.22U_0201_6.3V6K  [C_0201]  30.28 91.46 90 bottom
CT6  0.22U_0201_6.3V6K  [C_0201]  32 89.7 270 bottom
CT7  0.22U_0201_6.3V6K  [C_0201]  31.43 89.7 270 bottom
CT8  0.22U_0201_6.3V6K  [C_0201]  28.99 89.82 270 bottom
CT9  0.22U_0201_6.3V6K  [C_0201]  29.56 89.82 270 bottom
CT10  0.1U_0201_10V6K  [C_0201]  37.5 101.7 180 bottom
CT11  0.1U_0201_10V6K  [C_0201]  37.5 101.13 180 bottom
CT12  0.1U_0201_10V6K  [C_0201]  39.22 100.55 180 bottom
CT13  0.1U_0201_10V6K  [C_0201]  39.22 99.98 180 bottom
CT14  0.1U_0201_10V6K  [C_0201]  37.5 99.66 180 bottom
CT15  0.1U_0201_10V6K  [C_0201]  37.5 99.09 180 bottom
CT16  0.1U_0201_10V6K  [C_0201]  39.22 98.71 180 bottom
CT17  0.1U_0201_10V6K  [C_0201]  39.22 98.14 180 bottom
CT18  0.1U_0201_10V6K  [C_0201]  37.5 103.72 180 bottom
CT19  0.1U_0201_10V6K  [C_0201]  37.5 104.3 180 bottom
CT20  27P_0402_50V8J  [C_0402]  20.76 90.42 0 bottom
CT21  27P_0402_50V8J  [C_0402]  19.92 90.43 180 bottom
CT25  1U_0201_6.3V6M  [C_0201]  28.04 102.3 0 top
CT26  1U_0201_6.3V6M  [C_0201]  27.49 100.91 0 top
CT27  1U_0201_6.3V6M  [C_0201]  27.43 99.07 0 top
CT28  1U_0201_6.3V6M  [C_0201]  30.61 98.25 180 top
CT29  1U_0201_6.3V6M  [C_0201]  32.03 99.82 90 top
CT30  1U_0201_6.3V6M  [C_0201]  26.71 101.74 90 top
CT31  1U_0201_6.3V6M  [C_0201]  32.03 98.03 270 top
CT32  1U_0201_6.3V6M  [C_0201]  29.88 97.14 270 top
CT33  1U_0201_6.3V6M  [C_0201]  28.78 97.61 180 top
CT34  1U_0201_6.3V6M  [C_0201]  27.31 94.62 180 top
CT35  1U_0201_6.3V6M  [C_0201]  28.37 94.62 0 top
CT36  1U_0201_6.3V6M  [C_0201]  28.37 94.05 0 top
CT37  1U_0201_6.3V6M  [C_0201]  27.31 94.05 180 top
CT38  1U_0201_6.3V6M  [C_0201]  29.25 99.62 270 top
CT39  1U_0201_6.3V6M  [C_0201]  28.71 100.34 180 top
CT40  1U_0201_6.3V6M  [C_0201]  29.91 100.91 0 top
CT41  1U_0201_6.3V6M  [C_0201]  29.91 101.59 0 top
CT42  1U_0201_6.3V6M  [C_0201]  24.55 102.21 180 top
CT43  1U_0201_6.3V6M  [C_0201]  25.14 100.99 180 top
CT44  10U_0402_6.3V6M  [C_0402]  18.43 103.58 90 bottom
CT45  10U_0402_6.3V6M  [C_0402]  17.54 103.58 90 bottom
CT46  10U_0402_6.3V6M  [C_0402]  16.65 103.58 90 bottom
CT47  10U_0402_6.3V6M  [C_0402]  15.76 103.58 90 bottom
CT48  1U_0201_6.3V6M  [C_0201]  25.43 98.89 270 top
CT49  1U_0201_6.3V6M  [C_0201]  23.58 100.11 90 top
CT50  1U_0201_6.3V6M  [C_0201]  22.95 100.11 90 top
CT51  1U_0201_6.3V6M  [C_0201]  22.31 100.11 90 top
CT52  1U_0201_6.3V6M  [C_0201]  22.9 97.86 0 top
CT53  1U_0201_6.3V6M  [C_0201]  22.9 98.44 0 top
CT54  1U_0201_6.3V6M  [C_0201]  22.91 99.02 0 top
CT55  47U_0603_6.3V6M  [C_0603]  18.15 108.81 180 bottom
CT56  47U_0603_6.3V6M  [C_0603]  18.15 106.39 180 bottom
CT57  47U_0603_6.3V6M  [C_0603]  18.15 107.6 180 bottom
CT59  10U_0402_6.3V6M  [C_0402]  22.07 92.41 180 top
CT60  10U_0402_6.3V6M  [C_0402]  22.93 93.04 0 top
CT61  1U_0201_6.3V6M  [C_0201]  24.04 97.1 180 top
CT62  1U_0201_6.3V6M  [C_0201]  25.59 99.59 0 top
CT63  1U_0201_6.3V6M  [C_0201]  26.09 96.34 180 top
CT64  1U_0201_6.3V6M  [C_0201]  26.06 97.68 180 top
CT67  1U_0402_6.3V6K  [C_0402]  33.93 91.15 270 bottom
CT68  47U_0805_6.3V6M  [C_0805]  35.03 92.24 0 bottom
CT69  47U_0805_6.3V6M  [C_0805]  34.95 90.5 0 bottom
CT70  .1U_0402_16V7K  [C_0402]  29.23 69.56 270 top
CT71  2.2U_0402_16V6K  [C_0402]  33.3 75.84 270 bottom
CT72  2.2U_0402_16V6K  [C_0402]  35.56 78.55 270 bottom
CT73  2.2U_0402_16V6K  [C_0402]  28.15 76.86 270 bottom
CT74  1U_0402_10V6K  [C_0402]  35.25 74.56 0 bottom
CT75  22U_0805_25V6M  [C_0805]  27.79 86.12 270 top
CT76  22U_0805_25V6M  [C_0805]  29.94 86.08 270 top
CT77  22U_0805_25V6M  [C_0805]  29.18 87.35 90 top
CT78  22U_0805_25V6M  [C_0805]  31.68 86.88 90 top
CT80  0.1U_0201_10V6K  [C_0201]  28.92 73.63 90 bottom
CT81  0.1U_0201_10V6K  [C_0201]  28.34 73.63 90 bottom
CT82  1U_0603_50V6K  [C_0603]  28.47 85.99 90 bottom
CT83  1U_0402_10V6K  [C_0402]  29.81 76.73 270 bottom
CT84  10U_0603_6.3V6M  [C_0603]  31.33 75.96 270 bottom
CT85  820PF_0402_50V7K  [C_0402]  25.21 86.26 90 bottom
CT86  820PF_0402_50V7K  [C_0402]  25.23 83.81 90 bottom
CT87  0.22U_0402_16V7K  [C_0402]  29.3 81.47 90 top
CT88  0.1U_0201_10V6K  [C_0201]  19.94 68.91 180 top
CT89  1U_0402_10V6K  [C_0402]  20.23 68.15 180 top
CT90  1U_0402_10V6K  [C_0402]  22.01 67.19 180 top
CT91  2.2U_0603_25V6K  [C_0603]  24.85 65.73 90 bottom
CT92  0.1U_0402_25V6K  [C_0402]  23.14 65.72 90 bottom
CT93  1U_0402_10V6K  [C_0402]  23.33 72.13 90 bottom
CT94  1U_0603_50V6K  [C_0603]  19.96 74.55 0 bottom
CT95  0.22U_0201_6.3V6K  [C_0201]  19.43 96.77 180 top
CT96  0.22U_0201_6.3V6K  [C_0201]  19.43 96.2 180 top
CT97  0.22U_0201_6.3V6K  [C_0201]  18.65 97.93 180 bottom
CT98  0.22U_0201_6.3V6K  [C_0201]  18.66 98.51 180 bottom
CT99  0.47U_0201_25V  [C_0201]  9.87 108.41 0 bottom
CT100  0.47U_0201_25V  [C_0201]  8.79 110.67 90 bottom
CT101  0.47U_0201_25V  [C_0201]  9.85 105.62 0 bottom
CT102  0.47U_0201_25V  [C_0201]  9.85 105.04 0 bottom
CT123  0.22U_0201_6.3V6K  [C_0201]  28.44 91.46 90 bottom
CT124  0.22U_0201_6.3V6K  [C_0201]  27.86 91.46 90 bottom
CT125  0.22U_0201_6.3V6K  [C_0201]  25.68 91.45 90 bottom
CT126  0.22U_0201_6.3V6K  [C_0201]  26.25 91.45 90 bottom
CT127  0.22U_0201_6.3V6K  [C_0201]  26.79 89.83 270 bottom
CT128  0.22U_0201_6.3V6K  [C_0201]  27.36 89.83 270 bottom
CT129  0.22U_0201_6.3V6K  [C_0201]  25.03 89.83 270 bottom
CT130  0.22U_0201_6.3V6K  [C_0201]  25.6 89.83 270 bottom
CT168  0.1U_0201_10V6K  [C_0201]  37.47 94.91 180 bottom
CT169  0.1U_0201_10V6K  [C_0201]  37.55 102.85 180 bottom
CT170  0.1U_0201_10V6K  [C_0201]  37.44 93.48 180 bottom
CT171  0.1U_0201_10V6K  [C_0201]  39.14 96.77 180 bottom
CT172  0.1U_0201_10V6K  [C_0201]  39.14 96.2 180 bottom
CT173  0.1U_0201_10V6K  [C_0201]  37.44 94.12 180 bottom
CT174  0.1U_0201_10V6K  [C_0201]  37.47 95.48 180 bottom
CT175  0.1U_0201_10V6K  [C_0201]  37.55 102.28 180 bottom
CT176  0.1U_0201_10V6K  [C_0201]  37.53 97.07 180 bottom
CT177  0.1U_0201_10V6K  [C_0201]  37.53 97.64 180 bottom
CT189  12P_0402_50V8J  [C_0402]  9.99 110.62 90 bottom
CT201  1P_0201_50V8C  [C_0201]  21.23 76.93 90 bottom
CT202  1P_0201_50V8C  [C_0201]  21.23 78.77 90 bottom
CT203  1P_0201_50V8C  [C_0201]  21.23 82.38 90 bottom
CT204  1P_0201_50V8C  [C_0201]  21.23 80.62 90 bottom
CV1  0.1U_0402_25V6  [C_0402]  66.95 128.97 90 top
CV2  0.1U_0402_25V6  [C_0402]  67.84 128.97 90 top
CV3  0.1U_0402_25V6  [C_0402]  68.73 128.97 90 top
CV4  0.1U_0402_25V6  [C_0402]  69.62 128.97 90 top
CV5  0.1U_0402_25V6  [C_0402]  70.51 128.97 90 top
CV6  0.1U_0402_25V6  [C_0402]  71.4 128.97 90 top
CV11  0.1U_0603_50V7K  [C_0603]  58.57 132.34 90 top
CV12  0.1U_0201_10V6K  [C_0201]  66 131.2 0 top
CV13  1000P_0402_50V7K  [C_0402]  42.19 123.72 270 top
CV14  0.01U_0402_50V7K  [C_0402]  43.08 124.59 90 top
CV15  0.1U_0603_50V7K  [C_0603]  45.55 126.69 180 top
CV16  10U_0603_10V6M  [C_0603]  65.24 128.92 180 top
CV17  0.01UF_0402_25V7K  [C_0402]  67.97 122.49 90 top
CV18  12P_0402_50V8J  [C_0402]  50.79 130.44 180 top
CV19  82P_0402_50V8J  [C_0402]  50.79 129.56 180 top
CV20  12P_0402_50V8J  [C_0402]  64.74 130.88 180 top
CV21  82P_0402_50V8J  [C_0402]  64.74 130 180 top
CV22  12P_0402_50V8J  [C_0402]  56.55 128.37 180 top
CV23  82P_0402_50V8J  [C_0402]  56.55 127.48 180 top
CV24  12P_0402_50V8J  [C_0402]  60.6 132.4 90 top
CV25  82P_0402_50V8J  [C_0402]  59.71 132.4 90 top
CV31  0.1U_0402_25V6  [C_0402]  20.54 76.78 180 bottom
CV32  0.1U_0402_25V6  [C_0402]  20.54 77.67 180 bottom
CV33  0.1U_0402_25V6  [C_0402]  20.54 78.62 180 bottom
CV34  0.1U_0402_25V6  [C_0402]  20.54 79.51 180 bottom
CV35  0.1U_0402_25V6  [C_0402]  20.54 82.23 180 bottom
CV36  0.1U_0402_25V6  [C_0402]  20.54 83.12 180 bottom
CV37  0.1U_0402_25V6  [C_0402]  19.63 80.46 0 bottom
CV38  0.1U_0402_25V6  [C_0402]  19.63 81.35 0 bottom
CV39  0.1U_0201_10V6K  [C_0201]  11.83 99.1 90 bottom
CV40  0.1U_0201_10V6K  [C_0201]  15.39 88.25 270 top
CV41  10U_0603_10V6M  [C_0603]  11.83 95.2 0 bottom
CV635  0.1U_0402_25V6K  [C_0402]  50.62 126.95 0 top
CZ1  0.1U_0201_10V6K  [C_0201]  56.51 129.11 180 top
CZ2  0.1U_0201_10V6K  [C_0201]  50.73 131.2 180 top
CZ3  100P_0402_50V8J  [C_0402]  39.41 127.07 180 bottom
CZ12  0.1U_0402_25V6  [C_0402]  229.96 72.34 0 bottom
CZ13  0.1U_0402_25V6  [C_0402]  229.96 71.45 0 bottom
CZ17  .047U_0402_16V7K  [C_0402]  237.74 93.65 0 top
CZ18  .047U_0402_16V7K  [C_0402]  237.74 94.54 0 top
CZ19  33P_0402_50V8J  [C_0402]  237.74 95.43 0 top
CZ20  22U_0603_6.3V6M  [C_0603]  237.58 109.03 180 top
CZ21  33P_0402_50V8J  [C_0402]  237.74 96.32 0 top
CZ23  47P_0402_50V8J  [C_0402]  237.59 110.06 180 top
CZ24  100P_0402_50V8J  [C_0402]  237.59 110.95 180 top
CZ25  2200P_0402_50V7K  [C_0402]  237.59 111.83 180 top
CZ26  100U_B2_6.3VM_R35M  [C_B2]  235.23 89.14 90 bottom
CZ27  10U_0603_10V6M  [C_0603]  241.6 79.93 180 top
CZ28  0.01UF_0402_25V7K  [C_0402]  241.36 77.98 180 top
CZ29  0.01UF_0402_25V7K  [C_0402]  241.36 78.87 180 top
CZ30  0.1U_0201_10V6K  [C_0201]  241.23 80.91 180 top
CZ31  0.1U_0201_10V6K  [C_0201]  241.11 61.73 180 top
CZ32  4.7U_0603_6.3V6K  [C_0603]  246.85 106.12 90 top
CZ33  15P_0402_50V8J  [C_0402]  241.34 62.49 180 top
CZ34  15P_0402_50V8J  [C_0402]  241.34 63.38 180 top
CZ35  15P_0402_50V8J  [C_0402]  244.88 106.23 90 top
CZ36  15P_0402_50V8J  [C_0402]  245.77 106.23 90 top
CZ37  4.7U_0402_6.3V6M  [C_0402]  278.53 62.06 270 bottom
CZ38  47P_0402_50V8J  [C_0402]  278.53 57.59 90 bottom
CZ39  33P_0402_50V8J  [C_0402]  278.53 56.68 270 bottom
CZ40  33P_0402_50V8J  [C_0402]  278.53 60.29 270 bottom
CZ41  0.1U_0402_25V6  [C_0402]  277.65 62.06 270 bottom
CZ50  0.1U_0201_10V6K  [C_0201]  161.42 114.01 180 bottom
CZ51  0.1U_0201_10V6K  [C_0201]  158.77 114.53 90 bottom
CZ52  10U_0603_10V6M  [C_0603]  157.77 114.1 90 bottom
CZ53  0.1U_0201_10V6K  [C_0201]  162.93 107.71 0 bottom
CZ54  0.1U_0201_10V6K  [C_0201]  157.25 105.59 270 bottom
CZ55  10U_0603_10V6M  [C_0603]  163.02 106.76 0 bottom
CZ56  0.1U_0402_25V6  [C_0402]  160.96 105.6 270 bottom
CZ57  12P_0402_50V8J  [C_0402]  155.13 112.82 180 bottom
CZ58  68P_0402_50V8J  [C_0402]  155.13 111.93 180 bottom
CZ59  12P_0402_50V8J  [C_0402]  161.57 117.61 180 bottom
CZ60  68P_0402_50V8J  [C_0402]  161.57 118.5 180 bottom
CZ61  .047U_0402_16V7K  [C_0402]  224.67 58.57 270 top
CZ62  68P_0402_50V8J  [C_0402]  232.43 54.29 90 top
CZ63  68P_0402_50V8J  [C_0402]  232.43 53.43 270 top
CZ64  0.1U_0201_10V6K  [C_0201]  225.28 56.02 0 top
CZ66  0.1U_0201_10V6K  [C_0201]  223.45 56.02 180 top
CZ67  0.1U_0201_10V6K  [C_0201]  224.66 56.02 180 top
CZ68  0.1U_0201_10V6K  [C_0201]  225.44 58.49 270 top
CZ69  68P_0402_50V8J  [C_0402]  225.58 55.27 270 top
CZ71  68P_0402_50V8J  [C_0402]  223.29 55.33 270 top
CZ72  68P_0402_50V8J  [C_0402]  224.62 55.27 270 top
CZ73  68P_0402_50V8J  [C_0402]  226.2 58.57 270 top
CZ75  10U_0402_6.3V6M  [C_0402]  161.48 114.82 180 bottom
CZ76  12P_0402_50V8J  [C_0402]  163.31 105.53 180 top
CZ77  68P_0402_50V8J  [C_0402]  163.31 104.65 180 top
CZ78  100P_0402_50V8J  [C_0402]  236.02 58 180 top
CZ80  10P_0402_50V8J  [C_0402]  210.46 55.28 180 top
CZ81  10P_0402_50V8J  [C_0402]  212.25 56.6 180 top
CZ82  0.1U_0201_10V6K  [C_0201]  206.51 59.95 270 top
CZ83  68P_0402_50V8J  [C_0402]  208.67 56.21 0 top
CZ90  0.1U_0201_10V6K  [C_0201]  208.72 57.03 0 top
CZ91  0.1U_0201_10V6K  [C_0201]  205.94 59.95 270 top
CZ92  0.1U_0201_10V6K  [C_0201]  206.51 58.48 180 top
CZ93  0.1U_0201_10V6K  [C_0201]  265.71 84.82 270 top
CZ100  1U_0402_6.3V6K  [C_0402]  123.15 128.9 270 top
CZ101  0.1U_0201_10V6K  [C_0201]  126.14 126.45 270 top
CZ102  1U_0402_6.3V6K  [C_0402]  136.35 65.35 0 top
CZ103  0.1U_0201_10V6K  [C_0201]  137.02 70.31 0 top
CZ104  0.1U_0402_10V7K  [C_0402]  141.5 67.69 90 top
CZ105  1U_0402_6.3V6K  [C_0402]  118.77 128.87 270 top
CZ106  0.1U_0201_10V6K  [C_0201]  121.91 126.88 0 top
CZ109  470P_0402_50V7K  [C_0402]  248.7 110.88 180 top
CZ110  470P_0402_50V7K  [C_0402]  248.7 111.77 180 top
CZ111  0.1U_0201_10V6K  [C_0201]  249.86 113.29 0 top
CZ112  0.1U_0201_10V6K  [C_0201]  154.93 58.37 0 top
CZ113  470P_0402_50V7K  [C_0402]  155.29 59.89 180 top
CZ114  1000P_0402_50V7K  [C_0402]  155.29 60.78 180 top
CZ115  0.1U_0201_10V6K  [C_0201]  155 61.54 180 top
CZ116  0.1U_0201_10V6K  [C_0201]  275.97 89.61 180 top
CZ117  470P_0402_50V7K  [C_0402]  275.77 90.43 180 top
CZ118  470P_0402_50V7K  [C_0402]  275.77 91.39 180 top
CZ119  0.1U_0201_10V6K  [C_0201]  278.31 94.24 0 top
CZ120  0.1U_0201_10V6K  [C_0201]  210.59 51.29 270 top
CZ121  470P_0402_50V7K  [C_0402]  209.83 51.33 270 top
CZ122  0.1U_0201_10V6K  [C_0201]  248.54 109.8 180 top
CZ124  2200P_0402_50V7K  [C_0402]  275.77 92.28 180 top
CZ125  0.1U_0201_10V6K  [C_0201]  248.59 65.42 0 top
CZ126  1000P_0402_50V7K  [C_0402]  248.74 64.46 0 top
CZ127  220P_0402_50V7K  [C_0402]  248.74 63.57 0 top
CZ128  0.1U_0201_10V6K  [C_0201]  248.59 62.62 0 top
CZ197  470P_0402_50V7K  [C_0402]  204.87 51.37 90 top
CZ198  100P_0402_50V8J  [C_0402]  240.36 111.83 0 top
CZ200  0.1U_0402_25V6K  [C_0402]  54.81 126.57 0 top
DA1  AZ5123-02S.R7G_SOT23-3  [L03ESDL5V0CC3-2_SOT23-3]  281.75 36.33 90 bottom
DA2  AZ5125-02S.R7G_SOT23-3  [L03ESDL5V0CC3-2_SOT23-3]  281.68 30.3 90 bottom
DA3  AZ5123-02S.R7G_SOT23-3  [L03ESDL5V0CC3-2_SOT23-3]  290.43 45.22 270 bottom
DA6  -  [L03ESDL5V0CC3-2_SOT23-3]  280.29 23.76 90 bottom
DA7  -  [L03ESDL5V0CC3-2_SOT23-3]  280.29 19.82 90 bottom
DA8  RB751S40T1G_SOD523-2  [AZ5125-01HPR7G_SOD523-2]  262.77 69.85 270 top
DC1  RB751S40T1G_SOD523-2  [AZ5125-01HPR7G_SOD523-2]  154.84 123.34 90 bottom
DC2  RB751S40T1G_SOD523-2  [AZ5125-01HPR7G_SOD523-2]  153.69 124.84 270 bottom
DE1  BZV55-B5V6_SOD80C2  [BZV55-B5V1_SOD80C2]  239.38 120.46 90 bottom
DE2  RB751S40T1G_SOD523-2  [AZ5125-01HPR7G_SOD523-2]  239.83 100.22 180 top
DI1  AZ1045-04F_DFN2510P10E-10-9  [L05ESDL5V0NA-4_SLP2510P8-10-9]  20.08 62.32 270 top
DI2  PESD5V0U2BT_SOT23-3  [AZC199-02SPR7G_SOT23-3]  21.04 59.42 180 bottom
DI4  AZ1045-04F_DFN2510P10E-10-9  [L05ESDL5V0NA-4_SLP2510P8-10-9]  279.75 84.07 90 top
DI5  PESD5V0U2BT_SOT23-3  [AZC199-02SPR7G_SOT23-3]  279.8 78.84 0 bottom
DT1  1N4148WS-L_SOD323-2  [1N4148WS-7-F_SOD323-2]  19.33 69.16 0 bottom
DT2  1N4148WS-L_SOD323-2  [1N4148WS-7-F_SOD323-2]  19.33 70.94 0 bottom
DT3  1N4148WS-L_SOD323-2  [1N4148WS-7-F_SOD323-2]  21.73 72.72 180 bottom
DT4  AZ4024-02S_SOT23-3  [L30ESD24VC3-2_SOT23-3]  19.2 112.95 0 top
DT5  AZ5B75-01B  [ESD8011MUT5G_X3DFN2-2-S]  11.71 110.41 90 top
DT6  AZ5B75-01B  [ESD8011MUT5G_X3DFN2-2-S]  11.71 109.7 270 top
DT9  AZ5B75-01B  [ESD8011MUT5G_X3DFN2-2-S]  11.64 103.49 90 top
DT10  AZ5B75-01B  [ESD8011MUT5G_X3DFN2-2-S]  11.64 102.78 270 top
DT13  AZ5B75-01B  [ESD8011MUT5G_X3DFN2-2-S]  11.71 110.41 90 bottom
DT14  AZ5B75-01B  [ESD8011MUT5G_X3DFN2-2-S]  11.71 109.7 270 bottom
DT17  AZ5B75-01B  [ESD8011MUT5G_X3DFN2-2-S]  11.64 102.78 270 bottom
DT18  AZ5B75-01B  [ESD8011MUT5G_X3DFN2-2-S]  11.64 103.49 90 bottom
DT39  AZ1045-04F_DFN2510P10E-10-9  [L05ESDL5V0NA-4_SLP2510P8-10-9]  11.64 107.57 90 top
DT40  AZ1045-04F_DFN2510P10E-10-9  [L05ESDL5V0NA-4_SLP2510P8-10-9]  12.51 107.56 90 bottom
DV1  -  [BAT54CW_SOT323-3]  72.61 125.87 90 top
DV2  -  [BAT54CW_SOT323-3]  72.61 123.33 90 top
DV3  -  [BAT54CW_SOT323-3]  69.43 124.09 90 top
DV4  -  [AZC199-02SPR7G_SOT23-3]  53.17 125.77 180 top
DV7  ESD8011MUT5G_X3DFN2-2  [ESD8011MUT5G_X3DFN2-2-S]  58.42 120.63 270 top
DV8  ESD8011MUT5G_X3DFN2-2  [ESD8011MUT5G_X3DFN2-2-S]  58.42 121.35 90 top
DZ1  RB751S40T1G_SOD523-2  [AZ5125-01HPR7G_SOD523-2]  243.69 65.69 180 top
DZ2  RB751S40T1G_SOD523-2  [AZ5125-01HPR7G_SOD523-2]  243.86 67.28 180 top
DZ5  RB751S40T1G_SOD523-2  [AZ5125-01HPR7G_SOD523-2]  240.93 109.48 180 top
DZ6  RB751S40T1G_SOD523-2  [AZ5125-01HPR7G_SOD523-2]  240.74 106.71 270 top
DZ7  RB751S40T1G_SOD523-2  [AZ5125-01HPR7G_SOD523-2]  220.63 57.29 90 top
DZ8  RB751S40T1G_SOD523-2  [AZ5125-01HPR7G_SOD523-2]  221.77 53.73 180 top
DZ9  -  [BAT54CW_SOT323-3]  250.81 123.02 180 bottom
FD1  FIDUCIAL MARK~D  [FIDUCIAL_C40M80]  31.52 51.64 0 top
FD2  FIDUCIAL MARK~D  [FIDUCIAL_C40M80]  278.15 126.88 0 top
FD3  FIDUCIAL MARK~D  [FIDUCIAL_C40M80]  76.6 127.33 0 bottom
FD4  FIDUCIAL MARK~D  [FIDUCIAL_C40M80]  278.6 27.06 180 bottom
H1  -  [H_3P4]  82.2 113.55 0 top
H2  -  [H_3P4]  142 113.55 0 top
H3  -  [H_3P4]  142 91.4 0 top
H4  -  [H_3P4]  82.2 91.4 0 top
H5  -  [H_1P0N]  93.45 115.46 0 top
H6  -  [H_1P0N]  134.56 92.35 0 top
H7  -  [H_3P2]  275.9 102.5 0 top
H8  -  [H_3P2]  266.9 71.4 0 top
H9  H_2P6  [H_2P6-G]  234.1 134.2 0 top
H10  H_3P8  [H_3P8-G]  150.1 51.1 0 top
H12  H_3P5  [H_3P5-G]  270.6 50.25 0 top
H14  H_2P6  [H_2P6-G]  5.55 115.6 0 top
H15  H_2P6  [H_2P6-G]  5.55 98.7 0 top
H16  H_2P6  [H_2P6-G]  279.9 13.95 0 top
H18  H_2P6  [H_2P6-G]  12.05 116.5 0 top
H20  H_3P1  [H_3P1-G]  296.1 26.3 0 top
H21  H_3P5  [H_3P5-G]  220.15 77.75 0 top
H22  H_3P5  [H_3P5-G]  168.6 112.45 0 top
H23  H_2P6  [H_2P6-G]  8.6 74.35 0 top
H24  H_2P6  [H_2P6-G]  4.6 49.5 0 top
H25  -  [H_3P2]  43.6 132.55 0 top
H26  -  [H_3P2]  78 132.55 0 top
H27  H_3P5  [H_3P5-G]  35.55 47.35 0 top
H28  H_3P5  [H_3P5-G]  67.1 51.15 0 top
H29  H_2P6  [H_2P6-G]  289.05 132.9 0 top
H30  -  [H_2P3X2P7N]  4.6 44.5 90 top
H33  H_2P6  [H_2P6-G]  286.4 68.2 0 top
H37  H_3P1  [H_3P1-G]  150.1 134.3 0 top
H38  H_2P6  [H_2P6-G]  164.1 134.2 0 top
H39  -  [H_2P3N]  290.6 26.3 0 top
JAPS1  CVILU_CF4218FH0R0-05-NH  [CVILU_CF4218FH0R0-05-NH_18P-T]  264.56 108.17 180 top
JDB1  ACES_50506-00641-P01  [ACES_50506-00641-P01_6P]  30.38 66.75 180 bottom
JDEG1  ACES 50506-01041-P01  [HB_A531015-SCHR21_10P]  290.85 126.34 270 bottom
JDIMM1  LCN_DAN05-Q0406-0103  [LCN_DAN05-Q0406-0103_260P]  76.22 61.9 180 bottom
JEDP1  ACES_50398-04041-001  [ACES_50398-04041-001_40P]  51.25 132.7 0 bottom
JESPI  ACES_50506-01041-P01  [ACES_50506-01041-P01_10P]  247.45 54.75 180 bottom
JFAN1  ACES_50271-0040N-001  [ACES_50271-0040N-001_4P]  236.55 122.66 90 bottom
JHDMI1  ACON_HMRBL-A41L0F  [ACON_HMRBL-A41L0F_19P-T]  11.45 81.1 90 bottom
JHP1  SINGA_2SJ3095-085111F  [SINGA_2SJ3095-085111F_6P]  287.5 41.1 90 bottom
JIR1  E-T_4251K-F06N-40L  [E-T_4251K-F06N-40L_6P]  38.41 129.9 90 bottom
JKBTP1  CVILU_CF5020FD0RK-05-NH  [CVILU_CF5020FD0RK-05-NH_20P-T]  214.05 59.03 180 bottom
JLED1  ACES_50209-0060N-P01  [ACES_50209-0060N-P01_6P]  289.47 8.51 270 bottom
JLOM1  SANTA_130470-19  [SANTA_130470-19_13P-T]  283.87 100.18 270 bottom
JNGFF1  LCN_DAN05-67306-0100  [LCN_DAN05-67306-0100_75P]  233.37 80.65 270 bottom
JNGFF2  BELLW_80149-3221  [BELLW_80149-3221_67P]  230.37 111.75 270 bottom
JNGFF3  LOTES_APCI0170-P001A  [LOTES_APCI0170-P001A_75P]  28.95 43.85 180 bottom
JRTC1  ACES_50271-0020N-001  [ACES_50271-0020N-001_2P]  283.95 9.3 180 bottom
JSD1  T-SOL_158-1240902600  [T-SOL_158-1240902600_23P-T]  286.05 59.37 90 top
JSIM1  JAE_SF51S006V4DR1000Q  [JAE_SF51S006V4DR1000Q_8P]  284.73 61.35 270 bottom
JSPI1  CVILU_CF5020FD0R0-05-NH  [CVILU_CF5020FD0R0-05-NH_20P]  165.45 101.41 270 bottom
JSPK1  ACES_50278-0040N-001  [ACES_50278-0040N-001_4P]  286.02 19.15 270 bottom
JTAG1  @SHORT PADS~D  [SHORTPADS]  248.48 99.79 180 top
JUART1  CVILU_CI1804M1VRA-NH  [CVILU_CI1804M1VRA-NH_4P]  128.81 132.36 180 bottom
